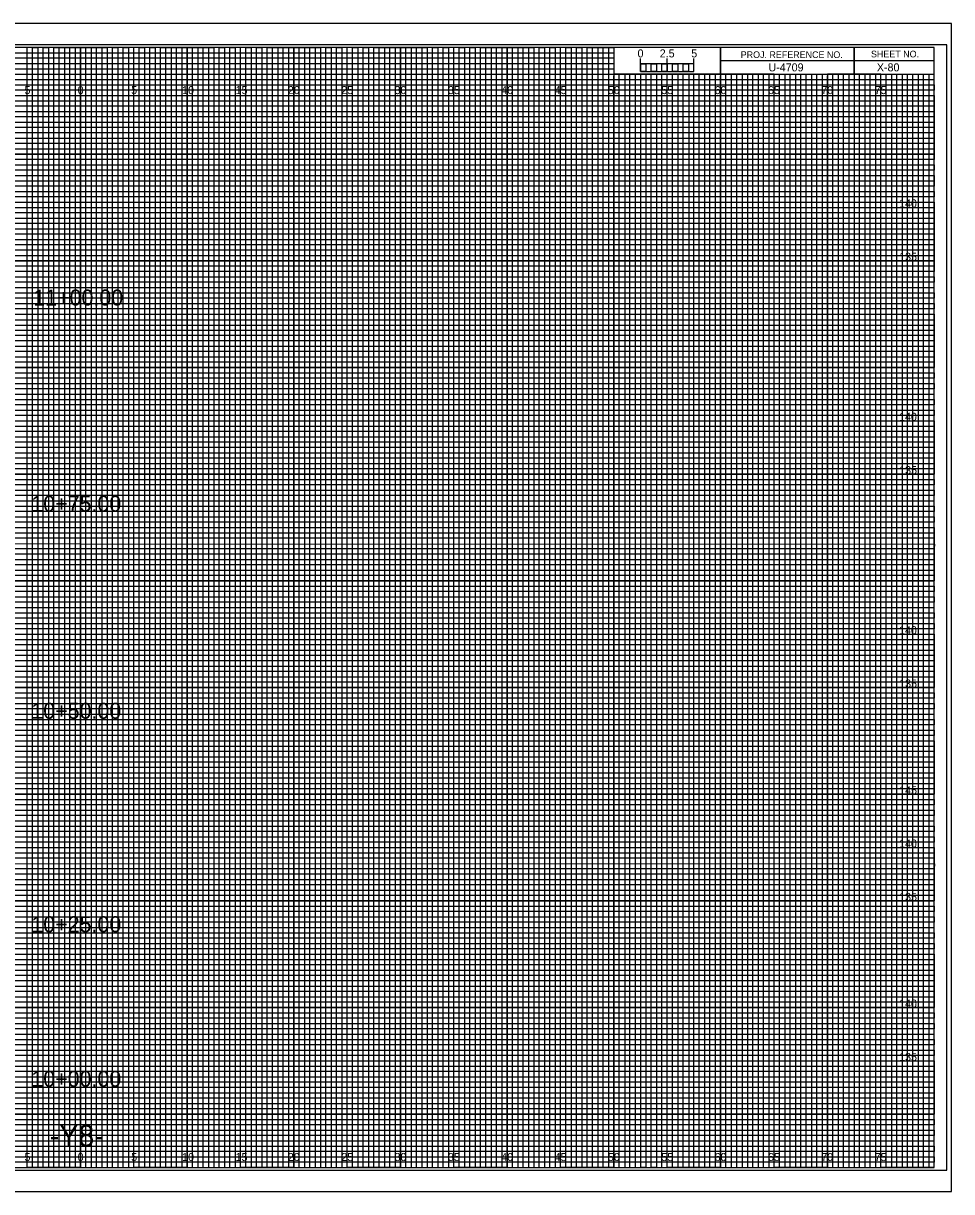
# Model space of a CAD drawing. Extents: x -7 to 162, y -2 to 107.
# Drawn here: x 74.6 to 161.7, y -2.3 to 107.3 of the extents above; entities that cross this region are included whole.
import ezdxf

# ---------------------------------------------------------------- set-up
doc = ezdxf.new("R2010")
doc.units = 0
for name, color, linetype in [('Prop CMT Conc Surface', 7, 'Continuous'), ('Prop CMT Concrete Structures', 7, 'Continuous'), ('Prop CMT Pvmt Course 1', 7, 'Continuous'), ('Prop CMT Pvmt Course 1 CG', 7, 'Continuous'), ('Prop CMT Pvmt Surface Shoulder', 7, 'Continuous'), ('Prop CMT Pvmt Wedge Surface 2', 7, 'Continuous'), ('Prop CMT Pvmt Wedge Surface 3', 7, 'Continuous'), ('Prop XS Alignment Label', 7, 'Continuous'), ('Prop XS Bar Scale Labels', 7, 'Continuous'), ('Prop XS Ditch Standard Text', 7, 'Continuous'), ('Prop XS Hydro Elevations', 7, 'Continuous'), ('Prop XS Project Number', 7, 'Continuous'), ('Prop XS Retaining Wall', 7, 'Continuous'), ('Prop XS SE Text', 7, 'Continuous'), ('Prop XS Sheet Number', 7, 'Continuous'), ('Prop XS Side Slope Text', 7, 'Continuous'), ('Prop XS Station Labels', 7, 'Continuous')]:
    doc.layers.add(name, color=color, linetype=linetype)

msp = doc.modelspace()

# ---------------------------------------------------------------- linework, layer by layer
at = {"layer": 'Prop CMT Conc Surface'}
for p, q in [((152.5, 105), (152.5, 102.5)), ((152.5, 102.5), (152.5, 105)), ((160, 103.75), (140, 103.75)), ((140, 103.75), (140, 102.5)), ((140, 102.5), (160, 102.5))]:
    msp.add_line(p, q, dxfattribs=at)
for points in [[(160, 105), (0, 105), (0, 0), (160, 0)], [(140, 105), (130, 105), (130, 102.52), (140, 102.52)], [(160, 105), (140, 105), (140, 102.5), (160, 102.5)]]:
    msp.add_lwpolyline(points, close=True, dxfattribs=at)
at = {"layer": 'Prop CMT Concrete Structures'}
for p, q in [((133.5, 102.5), (133, 102.5)), ((133, 102.5), (133, 0)), ((133.5, 0), (133.5, 102.5)), ((134.5, 102.5), (134, 102.5)), ((134, 102.5), (134, 0)), ((134.5, 0), (134.5, 102.5)), ((133, 0), (132.5, 0)), ((134, 0), (133.5, 0))]:
    msp.add_line(p, q, dxfattribs=at)
for points in [[(75, 0), (75.5, 0), (75.5, 105), (76, 105), (76, 0)], [(76, 0), (76.5, 0), (76.5, 105), (77, 105), (77, 0)], [(77.5, 0), (78, 0), (78, 105), (78.5, 105), (78.5, 0)], [(78.5, 0), (79, 0), (79, 105), (79.5, 105), (79.5, 0)], [(80, 0), (80.5, 0), (80.5, 105), (81, 105), (81, 0)], [(81, 0), (81.5, 0), (81.5, 105), (82, 105), (82, 0)], [(82.5, 0), (83, 0), (83, 105), (83.5, 105), (83.5, 0)], [(83.5, 0), (84, 0), (84, 105), (84.5, 105), (84.5, 0)], [(85, 0), (85.5, 0), (85.5, 105), (86, 105), (86, 0)], [(86, 0), (86.5, 0), (86.5, 105), (87, 105), (87, 0)], [(87.5, 0), (88, 0), (88, 105), (88.5, 105), (88.5, 0)], [(88.5, 0), (89, 0), (89, 105), (89.5, 105), (89.5, 0)], [(90, 0), (90.5, 0), (90.5, 105), (91, 105), (91, 0)], [(91, 0), (91.5, 0), (91.5, 105), (92, 105), (92, 0)], [(92.5, 0), (93, 0), (93, 105), (93.5, 105), (93.5, 0)], [(93.5, 0), (94, 0), (94, 105), (94.5, 105), (94.5, 0)], [(95, 0), (95.5, 0), (95.5, 105), (96, 105), (96, 0)], [(96, 0), (96.5, 0), (96.5, 105), (97, 105), (97, 0)], [(97.5, 0), (98, 0), (98, 105), (98.5, 105), (98.5, 0)], [(98.5, 0), (99, 0), (99, 105), (99.5, 105), (99.5, 0)], [(100, 0), (100.5, 0), (100.5, 105), (101, 105), (101, 0)], [(101, 0), (101.5, 0), (101.5, 105), (102, 105), (102, 0)], [(102.5, 0), (103, 0), (103, 105), (103.5, 105), (103.5, 0)], [(103.5, 0), (104, 0), (104, 105), (104.5, 105), (104.5, 0)], [(105, 0), (105.5, 0), (105.5, 105), (106, 105), (106, 0)], [(106, 0), (106.5, 0), (106.5, 105), (107, 105), (107, 0)], [(107.5, 0), (108, 0), (108, 105), (108.5, 105), (108.5, 0)], [(108.5, 0), (109, 0), (109, 105), (109.5, 105), (109.5, 0)], [(110, 0), (110.5, 0), (110.5, 105), (111, 105), (111, 0)], [(111, 0), (111.5, 0), (111.5, 105), (112, 105), (112, 0)], [(112.5, 0), (113, 0), (113, 105), (113.5, 105), (113.5, 0)], [(113.5, 0), (114, 0), (114, 105), (114.5, 105), (114.5, 0)], [(115, 0), (115.5, 0), (115.5, 105), (116, 105), (116, 0)], [(116, 0), (116.5, 0), (116.5, 105), (117, 105), (117, 0)], [(117.5, 0), (118, 0), (118, 105), (118.5, 105), (118.5, 0)], [(118.5, 0), (119, 0), (119, 105), (119.5, 105), (119.5, 0)], [(120, 0), (120.5, 0), (120.5, 105), (121, 105), (121, 0)], [(121, 0), (121.5, 0), (121.5, 105), (122, 105), (122, 0)], [(122.5, 0), (123, 0), (123, 105), (123.5, 105), (123.5, 0)], [(123.5, 0), (124, 0), (124, 105), (124.5, 105), (124.5, 0)], [(125, 0), (125.5, 0), (125.5, 105), (126, 105), (126, 0)], [(126, 0), (126.5, 0), (126.5, 105), (127, 105), (127, 0)], [(127.5, 0), (128, 0), (128, 105), (128.5, 105), (128.5, 0)], [(128.5, 0), (129, 0), (129, 105), (129.5, 105), (129.5, 0)], [(130, 0), (130.5, 0), (130.5, 102.5), (131.01, 102.5), (131.01, 0)], [(131, 0), (131.5, 0), (131.5, 102.5), (132, 102.5), (132, 0)], [(135, 0), (135.49, 0), (135.49, 102.5), (136, 102.5), (136, 0)], [(136, 0), (136.5, 0), (136.5, 102.5), (137.03, 102.5), (137.03, 0)], [(137.5, 0), (138, 0), (138, 102.5), (138.5, 102.5), (138.5, 0)], [(138.5, 0), (139, 0), (139, 102.5), (139.5, 102.5), (139.5, 0)], [(140, 0), (140.5, 0), (140.5, 102.5), (141, 102.5), (141, 0)], [(141, 0), (141.5, 0), (141.5, 102.5), (142, 102.5), (142, 0)], [(142.5, 0), (143, 0), (143, 102.5), (143.5, 102.5), (143.5, 0)], [(143.5, 0), (144, 0), (144, 102.5), (144.5, 102.5), (144.5, 0)], [(145, 0), (145.5, 0), (145.5, 102.5), (146, 102.5), (146, 0)], [(146, 0), (146.5, 0), (146.5, 102.5), (147, 102.5), (147, 0)], [(147.5, 0), (148, 0), (148, 102.5), (148.5, 102.5), (148.5, 0)], [(148.5, 0), (149, 0), (149, 102.5), (149.5, 102.5), (149.5, 0)], [(150, 0), (150.5, 0), (150.5, 102.5), (151, 102.5), (151, 0)], [(151, 0), (151.5, 0), (151.5, 102.5), (152, 102.5), (152, 0)], [(152.5, 0), (153, 0), (153, 102.5), (153.5, 102.5), (153.5, 0)], [(153.5, 0), (154, 0), (154, 102.5), (154.5, 102.5), (154.5, 0)], [(155, 0), (155.5, 0), (155.5, 102.5), (156, 102.5), (156, 0)], [(156, 0), (156.5, 0), (156.5, 102.5), (157, 102.5), (157, 0)], [(157.5, 0), (158, 0), (158, 102.5), (158.5, 102.5), (158.5, 0)], [(158.5, 0), (159, 0), (159, 102.5), (159.5, 102.5), (159.5, 0)]]:
    msp.add_lwpolyline(points, dxfattribs=at)
at = {"layer": 'Prop CMT Pvmt Course 1'}
for p, q in [((0, 104.5), (130, 104.5)), ((130, 104.5), (130, 103.99)), ((130, 103.99), (0, 103.99)), ((0, 103.5), (130, 103.5)), ((130, 102.95), (0, 102.95)), ((130, 103.5), (130, 102.95)), ((0, 102), (160, 102))]:
    msp.add_line(p, q, dxfattribs=at)
for points in [[(0, 101.5), (135, 101.5), (160, 101.5), (160, 101), (0, 101)], [(0, 100.5), (160, 100.5), (160, 99.5), (0, 99.5)], [(0, 99), (160, 99), (160, 98.5), (0, 98.49)], [(0, 98), (160, 98), (160, 97), (0, 97)], [(0, 96.5), (160, 96.5), (160, 96), (0, 96)], [(0, 95.5), (160, 95.5), (160, 94.5), (0, 94.5)], [(0, 94), (160, 94), (160, 93.5), (0, 93.5)], [(0, 93), (160, 93), (160, 92), (0, 92)], [(0, 91.5), (160, 91.5), (160, 91), (0, 91)], [(0, 90.5), (160, 90.5), (160, 89.5), (0, 89.5)], [(0, 89), (160, 89), (160, 88.5), (0, 88.5)], [(0, 88), (160, 88), (160, 86.98), (160, 86.5), (160, 86), (0, 86)], [(0, 87), (160, 87), (160, 86.5), (0, 86.5)], [(0, 85.5), (160, 85.5), (160, 84.5), (0, 84.52)], [(0, 84.52), (160, 84.5), (160, 84), (0, 84)], [(0, 83.5), (160, 83.5), (160, 83), (0, 83)], [(0, 82), (160, 82), (160, 81.5), (0, 81.5)], [(0, 81), (160, 81), (160, 80.5), (0, 80.5)], [(-0.04, 79.45), (160, 79.45), (160, 78.94), (-0.04, 78.94)], [(0, 78.5), (160, 78.5), (160, 78), (0, 78)], [(0, 77), (160, 77), (160, 76.5), (0, 76.5)], [(0, 76), (160, 76), (160, 75.5), (0, 75.5)], [(0, 74.5), (160, 74.5), (160, 74), (0, 74)], [(0, 73.5), (160, 73.5), (160, 73), (0, 73)], [(0, 72), (160, 72), (160, 71.5), (0, 71.5)], [(0, 71), (160, 71), (160, 70.5), (0, 70.5)], [(0, 69.5), (160, 69.5), (160, 68.99), (0, 69)], [(0, 68.5), (160, 68.5), (160, 68), (0, 68)], [(0, 67), (160, 67), (160, 66.5), (0, 66.5)], [(0, 66), (160, 66), (160, 65.5), (0, 65.5)], [(0, 64.5), (160, 64.5), (160, 64), (0, 64)], [(0, 63.5), (160, 63.5), (160, 63), (0, 63)], [(0, 62), (160, 62), (160, 61.5), (0, 61.5)], [(0, 61), (160, 61), (160, 60.5), (0, 60.5)], [(0, 59.5), (160, 59.5), (160, 59), (0, 59)], [(0, 58.5), (160.03, 58.45), (160, 58), (0, 58)], [(0, 57), (160, 57), (160, 56.5), (0, 56.5)], [(0, 56), (160, 56), (160, 55.5), (0, 55.5)], [(0, 54.5), (160, 54.5), (160, 54), (0, 54)], [(0, 53.5), (160, 53.5), (160, 53), (0, 53)], [(0, 52), (160, 52), (160, 51.5), (0, 51.5)], [(0, 51), (160, 51), (160, 50.5), (0, 50.5)], [(0, 49.5), (160, 49.5), (160, 49), (0, 49)], [(0, 48.5), (160, 48.5), (160, 48), (0, 48)], [(0, 47), (160, 47), (160, 46.5), (0, 46.5)], [(0, 46), (160, 46), (160, 45.5), (0, 45.5)], [(0, 44.5), (160, 44.5), (160, 44), (0, 44)], [(0, 43.5), (160, 43.5), (160, 43), (0, 43)], [(0, 42), (160, 42), (160, 41.5), (0, 41.5)], [(0, 41), (160, 41), (160, 40.5), (0, 40.5)], [(0, 39.5), (160, 39.5), (160, 38.99), (0, 39)], [(0, 38.5), (160, 38.5), (160, 38), (0, 38)], [(0, 37), (160, 37), (160, 36.5), (0, 36.5)], [(0, 36), (160, 36), (160, 35.5), (0, 35.5)], [(0, 34.5), (160, 34.5), (160, 34), (0, 34)], [(0, 33.5), (160, 33.5), (160, 33), (0, 33)], [(0, 32), (160, 32), (160, 31.5), (0, 31.5)], [(0, 31), (160, 31), (160, 30.5), (0, 30.5)], [(0, 29.5), (160, 29.5), (160, 29), (0, 29)], [(0, 28.5), (160.03, 28.46), (160, 28), (0, 28)], [(0, 27), (160, 27), (160, 26.5), (0, 26.5)], [(0, 26), (160, 26), (160, 25.5), (0, 25.5)], [(0, 24.5), (160, 24.5), (160, 24), (0, 24)], [(0, 23.5), (160, 23.5), (160, 23), (0, 23)], [(0, 22), (160, 22), (160, 21.5), (0, 21.5)], [(0, 21), (160, 21), (160, 20.5), (0, 20.5)], [(0, 19.5), (160, 19.5), (160, 19), (0, 19)], [(0, 18.5), (160, 18.5), (160, 18), (0, 18)], [(0, 17), (160, 17), (160, 16.5), (0, 16.5)], [(0, 16), (160, 16), (160, 15.5), (0, 15.5)], [(0, 14.5), (160, 14.5), (160, 14), (0, 14)], [(0, 13.5), (160, 13.5), (160, 13), (0, 13)], [(0, 12), (160, 12), (160, 11.5), (0, 11.5)], [(0, 11), (160, 11), (160, 10.5), (0, 10.5)], [(0, 9.5), (160, 9.5), (160, 9), (0, 9)], [(0, 8.5), (160, 8.5), (160, 8), (0, 8)], [(0, 7), (160, 7), (160, 6.5), (0, 6.5)], [(0, 6), (160, 6), (160, 5.5), (0, 5.5)], [(0, 4.5), (160, 4.5), (160, 4), (0, 4)], [(0, 3.5), (160, 3.5), (160, 3), (0, 3)], [(0, 2), (160, 2), (160, 1.5), (0, 1.5)], [(0, 1), (160, 1), (160, 0.5), (0, 0.5)]]:
    msp.add_lwpolyline(points, dxfattribs=at)
at = {"layer": 'Prop CMT Pvmt Course 1 CG'}
for p, q in [((132.5, 102.75), (132.5, 103.95)), ((132.5, 103.45), (132.5, 103.95)), ((135, 102.75), (135, 103.95)), ((137.5, 102.75), (137.5, 103.95)), ((137.5, 103.45), (137.5, 103.95))]:
    msp.add_line(p, q, dxfattribs=at)
for points in [[(137.5, 103.45), (132.5, 103.45), (132.5, 102.75), (137.5, 102.75)], [(132.5, 103.45), (133, 103.45), (133, 102.75), (132.5, 102.75)], [(133.5, 103.45), (134, 103.45), (134, 102.75), (133.5, 102.75)], [(134.5, 103.45), (135, 103.45), (135, 102.75), (134.5, 102.75)], [(135.5, 103.45), (136, 103.45), (136, 102.75), (135.5, 102.75)], [(136.5, 103.45), (137, 103.45), (137, 102.75), (136.5, 102.75)]]:
    msp.add_lwpolyline(points, close=True, dxfattribs=at)
at = {"layer": 'Prop CMT Pvmt Surface Shoulder'}
for points in [[(72.5, 0), (77.5, 0), (77.5, 105), (82.5, 105), (82.5, 0), (87.5, 0), (87.5, 105), (92.5, 105), (92.5, 0), (97.5, 0), (97.5, 105), (102.5, 105), (102.5, 0), (107.5, 0), (107.5, 105), (112.5, 105), (112.5, 0), (117.5, 0), (117.5, 105), (122.5, 105), (122.5, 0), (127.5, 0), (127.5, 105), (129.97, 105), (130, 105), (130, 102.5), (132.5, 102.5), (132.5, 0), (137.5, 0), (137.5, 102.5), (142.5, 102.5), (142.5, 0), (147.5, 0), (147.5, 102.5), (152.5, 102.5), (152.5, 0), (157.5, 0), (157.5, 102.5)], [(0, 102.5), (137.5, 102.5)], [(0, 92.5), (160, 92.5), (160, 97.5), (0, 97.5)], [(0, 82.5), (160, 82.5), (160, 87.5), (0, 87.5)], [(0, 72.5), (160, 72.5), (160, 77.5), (0, 77.5)], [(0, 62.5), (160, 62.5), (160, 67.5), (0, 67.5)], [(0, 52.5), (160, 52.5), (160, 57.5), (0, 57.5)], [(0, 42.5), (160, 42.5), (160, 47.5), (0, 47.5)], [(0, 32.5), (160, 32.5), (160, 37.5), (0, 37.5)], [(0, 22.5), (160, 22.5), (160, 27.5), (0, 27.5)], [(0, 12.5), (160, 12.5), (160, 17.5), (0, 17.5)], [(0, 2.5), (160, 2.5), (160, 7.5), (0, 7.5)]]:
    msp.add_lwpolyline(points, dxfattribs=at)
at = {"layer": 'Prop CMT Pvmt Wedge Surface 3'}
for p, q in [((75, 105), (70, 105)), ((75, 0), (75, 105)), ((85, 105), (80, 105)), ((80, 105), (80, 0)), ((85, 0), (85, 105)), ((95, 105), (90, 105)), ((90, 105), (90, 0)), ((95, 0), (95, 105)), ((105, 105), (100, 105)), ((100, 105), (100, 0)), ((105, 0), (105, 105)), ((115, 105), (110, 105)), ((110, 105), (110, 0)), ((115, 0), (115, 105)), ((125, 105), (120, 105)), ((120, 105), (120, 0)), ((125, 0), (125, 105)), ((130, 105), (130, 0)), ((135, 0), (135, 102.5)), ((145, 102.5), (140, 102.5)), ((140, 102.5), (140, 0)), ((145, 0), (145, 102.5)), ((155, 102.5), (150, 102.5)), ((150, 102.5), (150, 0)), ((155, 0), (155, 102.5)), ((80, 0), (75, 0)), ((90, 0), (85, 0)), ((100, 0), (95, 0)), ((110, 0), (105, 0)), ((120, 0), (115, 0)), ((130, 0), (125, 0)), ((140, 0), (135, 0)), ((150, 0), (145, 0)), ((160, 0), (155, 0)), ((160, 0), (160, 0))]:
    msp.add_line(p, q, dxfattribs=at)
for points in [[(0, 100), (160, 100), (160, 95), (0, 95)], [(0, 90), (160, 90), (160, 85), (0, 85)], [(0, 80), (160, 80), (160, 75), (0, 75)], [(0, 70), (160, 70), (160, 65), (0, 65)], [(0, 60), (160, 60), (160, 55), (0, 55)], [(0, 50), (160, 50), (160, 45), (0, 45)], [(0, 40), (160, 40), (160, 35), (0, 35)], [(0, 30), (160, 30), (160, 25), (0, 25)], [(0, 20), (160, 20), (160, 15), (0, 15)], [(0, 10), (160, 10), (160, 5), (0, 5)]]:
    msp.add_lwpolyline(points, dxfattribs=at)
at = {"layer": 'Prop XS Ditch Standard Text'}
for p, q in [((75, 0), (75, 105)), ((80, 0), (80, 105)), ((85, 0), (85, 105)), ((90, 0), (90, 105)), ((95, 0), (95, 105)), ((100, 0), (100, 105)), ((105, 0), (105, 105)), ((110, 0), (110, 105)), ((115, 0), (115, 105)), ((120, 0), (120, 105)), ((125, 0), (125, 105)), ((130, 0), (130, 102.34)), ((135, 0), (135, 102.34)), ((140, 0), (140, 102.34)), ((145, 0), (145, 102.34)), ((150, 0), (150, 102.34)), ((155, 0), (155, 102.34)), ((0, 100), (160, 100)), ((0, 95), (160, 95)), ((0, 90), (160, 90)), ((0, 85), (160, 85)), ((0, 80), (160, 80)), ((0, 75), (160, 75)), ((0, 70), (160, 70)), ((0, 65), (160, 65)), ((0, 60), (160, 60)), ((0, 55), (160, 55)), ((0, 50), (160, 50)), ((0, 45), (160, 45)), ((0, 40), (160, 40)), ((0, 35), (160, 35)), ((0, 30), (160, 30)), ((0, 25), (160, 25)), ((0, 20), (160, 20)), ((0, 15), (160, 15)), ((0, 10), (160, 10)), ((0, 5), (160, 5))]:
    msp.add_line(p, q, dxfattribs=at)
at = {"layer": 'Prop XS Hydro Elevations'}
for p, q in [((161.65, 107.25), (-6.7, 107.25)), ((-6.7, -2.25), (161.65, -2.25))]:
    msp.add_line(p, q, dxfattribs=at)
at = {"layer": 'Prop XS SE Text'}
msp.add_lwpolyline([(-5.4, -0.25), (161.2, -0.25), (161.2, 105.25), (-5.4, 105.25)], close=True, dxfattribs=at)
at = {"layer": 'Prop XS Side Slope Text'}
msp.add_lwpolyline([(-6.7, -2.25), (161.65, -2.25), (161.65, 107.25), (-6.7, 107.25)], close=True, dxfattribs=at)

# ---------------------------------------------------------------- texts
at = {"layer": 'Prop CMT Conc Surface'}
for s, p in [('PROJ. REFERENCE NO.', (141.88, 104)), ('SHEET NO.', (154.09, 104.06))]:
    msp.add_text(s, height=0.625, dxfattribs=at).set_placement(p)
at = {"layer": 'Prop CMT Pvmt Course 1 CG'}
msp.add_text('0', height=0.75, dxfattribs=at).set_placement((132.21, 104.06))
at = {"layer": 'Prop CMT Pvmt Wedge Surface 2'}
for s, p in [('5', (74.74, 100.62)), ('0', (79.73, 100.62)), ('0', (79.73, 100.62)), ('5', (84.74, 100.62)), ('10', (89.52, 100.62)), ('15', (94.53, 100.62)), ('20', (99.43, 100.62)), ('25', (104.44, 100.62)), ('30', (109.43, 100.62)), ('35', (114.44, 100.62)), ('40', (119.43, 100.62)), ('45', (124.44, 100.62)), ('50', (129.43, 100.62)), ('55', (134.44, 100.62)), ('60', (139.43, 100.62)), ('65', (144.44, 100.62)), ('70', (149.43, 100.62)), ('75', (154.44, 100.62)), ('5', (74.74, 0.62)), ('0', (79.73, 0.62)), ('0', (79.73, 0.62)), ('5', (84.74, 0.62)), ('10', (89.52, 0.62)), ('15', (94.53, 0.62)), ('20', (99.43, 0.62)), ('25', (104.44, 0.62)), ('30', (109.43, 0.62)), ('35', (114.44, 0.62)), ('40', (119.43, 0.62)), ('45', (124.44, 0.62)), ('50', (129.43, 0.62)), ('55', (134.44, 0.62)), ('60', (139.43, 0.62)), ('65', (144.44, 0.62)), ('70', (149.43, 0.62)), ('75', (154.44, 0.62))]:
    msp.add_text(s, height=0.75, dxfattribs=at).set_placement(p)
at = {"layer": 'Prop XS Alignment Label'}
msp.add_text('-Y8-', height=2, dxfattribs=at).set_placement((77.12, 2))
at = {"layer": 'Prop XS Bar Scale Labels'}
for s, p in [('2.5', (134.29, 104.06)), ('5', (137.24, 104.06))]:
    msp.add_text(s, height=0.75, dxfattribs=at).set_placement(p)
at = {"layer": 'Prop XS Project Number'}
msp.add_text('U-4709', height=0.75, dxfattribs=at).set_placement((144.48, 102.75))
at = {"layer": 'Prop XS Retaining Wall'}
for s, p in [('140', (156.72, 90)), ('135', (156.73, 85)), ('140', (156.72, 70)), ('135', (156.73, 65)), ('140', (156.72, 50)), ('135', (156.73, 45)), ('145', (156.73, 35)), ('140', (156.72, 30)), ('135', (156.73, 25)), ('140', (156.72, 15)), ('135', (156.73, 10))]:
    msp.add_text(s, height=0.75, dxfattribs=at).set_placement(p)
at = {"layer": 'Prop XS Sheet Number'}
msp.add_text('X-80', height=0.75, dxfattribs=at).set_placement((154.64, 102.75))
at = {"layer": 'Prop XS Station Labels'}
for s, p in [('11+00.00', (75.57, 80.8)), ('10+75.00', (75.39, 61.48)), ('10+50.00', (75.39, 42.07)), ('10+25.00', (75.39, 22.06)), ('10+00.00', (75.39, 7.58))]:
    msp.add_text(s, height=1.5, dxfattribs=at).set_placement(p)

doc.saveas('drawing.dxf')
